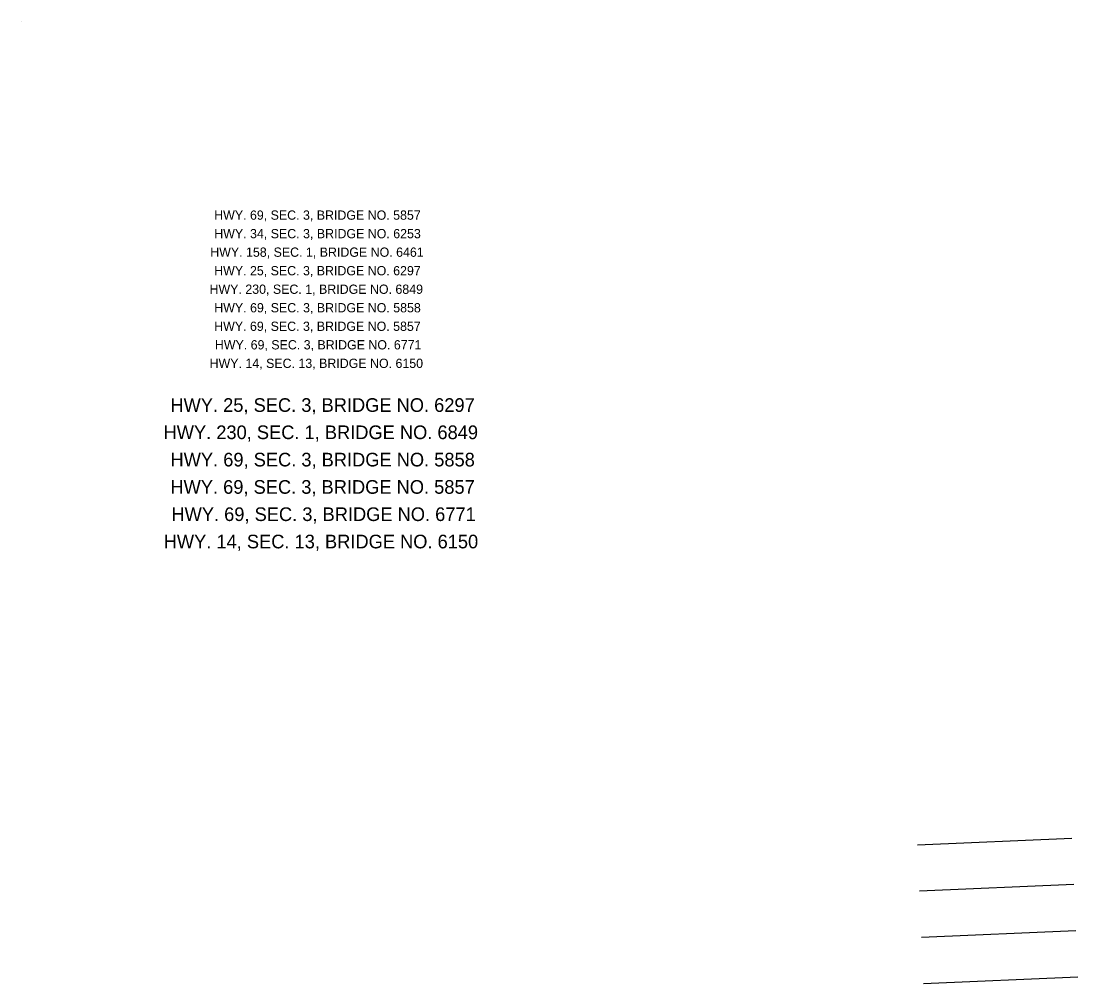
# Model space of a CAD drawing. Extents: x 1925873 to 1930787, y 596452 to 599617.
# Drawn here: x 1929418 to 1930787, y 596452 to 597699 of the extents above; entities that cross this region are included whole.
import ezdxf

# ---------------------------------------------------------------- set-up
doc = ezdxf.new("R2010")
doc.units = 0
for name, color, linetype in [('BR_Pr_Bent_CL', 7, 'Continuous'), ('Default', 7, 'Continuous'), ('R_Border Prem', 7, 'Continuous')]:
    doc.layers.add(name, color=color, linetype=linetype)

msp = doc.modelspace()

# ---------------------------------------------------------------- linework, layer by layer
at = {"layer": 'BR_Pr_Bent_CL'}
for p, q in [((1930779.3, 596640.3), (1930579.5, 596631.6)), ((1930781.9, 596580.4), (1930582.1, 596571.7)), ((1930784.5, 596520.4), (1930584.7, 596511.8)), ((1930787.1, 596460.5), (1930587.3, 596451.8))]:
    msp.add_line(p, q, dxfattribs=at)
at = {"layer": 'R_Border Prem'}
msp.add_line((1929418.3, 597699), (1929418.3, 597699), dxfattribs=at)

# ---------------------------------------------------------------- texts
at = {"layer": 'Default'}
for s, height, p in [('HWY. 69, SEC. 3, BRIDGE NO. 5857', 12, (1929668.4, 597441.7)), ('HWY. 34, SEC. 3, BRIDGE NO. 6253', 12, (1929668.5, 597417.7)), ('HWY. 158, SEC. 1, BRIDGE NO. 6461', 12, (1929663.3, 597393.7)), ('HWY. 25, SEC. 3, BRIDGE NO. 6297', 12, (1929668.4, 597369.7)), ('HWY. 230, SEC. 1, BRIDGE NO. 6849', 12, (1929662.4, 597345.7)), ('HWY. 69, SEC. 3, BRIDGE NO. 5858', 12, (1929668.5, 597321.7)), ('HWY. 69, SEC. 3, BRIDGE NO. 5857', 12, (1929668.4, 597297.7)), ('HWY. 69, SEC. 3, BRIDGE NO. 6771', 12, (1929669.3, 597273.7)), ('HWY. 14, SEC. 13, BRIDGE NO. 6150', 12, (1929662.5, 597249.7)), ('HWY. 25, SEC. 3, BRIDGE NO. 6297', 17.682, (1929611.7, 597192.8)), ('HWY. 230, SEC. 1, BRIDGE NO. 6849', 17.682, (1929602.8, 597157.5)), ('HWY. 69, SEC. 3, BRIDGE NO. 5858', 17.682, (1929611.8, 597122.1)), ('HWY. 69, SEC. 3, BRIDGE NO. 5857', 17.682, (1929611.7, 597086.7)), ('HWY. 69, SEC. 3, BRIDGE NO. 6771', 17.682, (1929613, 597051.4)), ('HWY. 14, SEC. 13, BRIDGE NO. 6150', 17.682, (1929603, 597016))]:
    msp.add_text(s, height=height, rotation=360, dxfattribs=at).set_placement(p)

doc.saveas('drawing.dxf')
